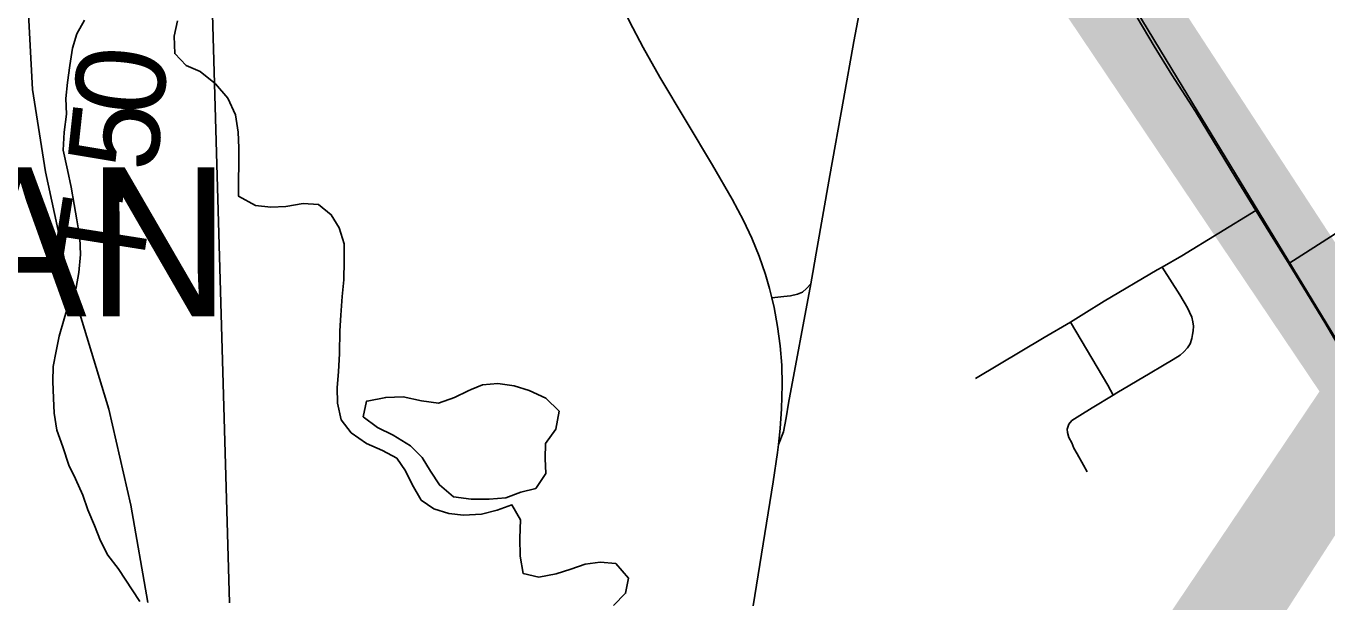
# Model space of a CAD drawing. Extents: x 0 to 34, y 0 to 22.
# Drawn here: x 24.267 to 25.094, y 15.37 to 15.736 of the extents above; entities that cross this region are included whole.
import ezdxf

# ---------------------------------------------------------------- set-up
doc = ezdxf.new("R2010")
doc.units = 0
for name, color, linetype in [('GM_X_City_Street', 7, 'Continuous'), ('GM_X_Corporation', 7, 'Continuous'), ('GM_X_Corporation_Text', 7, 'Continuous'), ('GM_X_Minor_Lake', 7, 'Continuous'), ('GM_X_Minor_River', 7, 'Continuous'), ('GM_X_Rail_Line', 7, 'Continuous'), ('GM_X_State_Location', 7, 'Continuous'), ('GM_X_State_Route', 7, 'Continuous'), ('GM_X_Township_Road_Text', 7, 'Continuous'), ('GM_X_US_Route', 7, 'Continuous'), ('SH_Text', 7, 'Continuous')]:
    doc.layers.add(name, color=color, linetype=linetype)

msp = doc.modelspace()

# ---------------------------------------------------------------- linework, layer by layer
at = {"layer": 'GM_X_City_Street'}
for points in [[(24.74536, 15.47013), (24.7487, 15.4782), (24.7504, 15.48722), (24.75186, 15.49649), (24.76593, 15.57224), (24.76719, 15.57943), (24.76935, 15.59172), (24.77803, 15.64122), (24.78684, 15.68955), (24.7933, 15.72624), (24.79909, 15.75669), (24.81704, 15.85353), (24.83005, 15.92365), (24.83706, 15.96719)], [(24.87069, 15.51205), (24.91425, 15.53818), (24.93116, 15.54787), (24.93955, 15.55322), (24.95246, 15.56119), (24.98618, 15.58112), (24.98927, 15.58282), (25.00193, 15.59016), (25.04895, 15.61884)], [(24.94166, 15.45285), (24.93934, 15.45695), (24.93524, 15.46426), (24.93328, 15.46783), (24.93187, 15.47123), (24.93005, 15.47469), (24.92915, 15.47777), (24.929, 15.48), (24.92998, 15.48305), (24.93186, 15.48538), (24.93693, 15.48867), (24.94493, 15.49342), (24.95814, 15.50152), (24.96055, 15.503), (24.98181, 15.51561), (24.98962, 15.52026), (24.99633, 15.52414), (25.00072, 15.52695), (25.00318, 15.52917), (25.00553, 15.53169), (25.0071, 15.53417), (25.00817, 15.53755), (25.0087, 15.54005), (25.00898, 15.54232), (25.00921, 15.54549), (25.00892, 15.54813), (25.00829, 15.55118), (25.00685, 15.55434), (25.00548, 15.55694), (25.00058, 15.56533), (24.98927, 15.58282)], [(24.74121, 15.56342), (24.74877, 15.56418), (24.75303, 15.5646), (24.7575, 15.56566), (24.76067, 15.56697), (24.7633, 15.56934), (24.76593, 15.57224)], [(24.95814, 15.50152), (24.95478, 15.50787), (24.93116, 15.54787)]]:
    msp.add_lwpolyline(points, dxfattribs=at)
at = {"layer": 'GM_X_Corporation'}
for points in [[(24.39649, 15.36959), (24.38041, 15.92726), (24.38056, 15.92741), (24.39462, 15.94223), (24.40352, 15.95099), (24.41056, 15.95718), (24.41794, 15.96294), (24.42562, 15.9683), (24.45188, 15.98487), (24.48106, 16.0025), (24.53434, 16.03428), (24.53774, 16.03643), (24.54532, 16.04049), (24.573, 16.05699), (24.59313, 16.06938), (24.53129, 16.17458), (24.52067, 16.16701), (24.50344, 16.24261), (24.48872, 16.26543)], [(25.16052, 15.64334), (25.0698, 15.58526), (25.09255, 15.54836), (25.10471, 15.52765)]]:
    msp.add_lwpolyline(points, dxfattribs=at)
at = {"layer": 'GM_X_Minor_Lake'}
for points in [[(24.48399, 15.49775), (24.48361, 15.49775), (24.4814, 15.48785), (24.49056, 15.48106), (24.50047, 15.47619), (24.51154, 15.46941), (24.51881, 15.46185), (24.52419, 15.45314), (24.52995, 15.44444), (24.53874, 15.43689), (24.55014, 15.43544), (24.56154, 15.43551), (24.57217, 15.43634), (24.58164, 15.43982), (24.59112, 15.44216), (24.59752, 15.45171), (24.59707, 15.46121), (24.59738, 15.47072), (24.60378, 15.47988), (24.60598, 15.4913), (24.59756, 15.49961), (24.58689, 15.50449), (24.57737, 15.50747), (24.56711, 15.50893), (24.55723, 15.5081), (24.55009, 15.50507)], [(24.55009, 15.50507), (24.54814, 15.50424), (24.53944, 15.50001), (24.5292, 15.49652), (24.51856, 15.49797), (24.50676, 15.50056), (24.49575, 15.50011), (24.48399, 15.49775)]]:
    msp.add_lwpolyline(points, dxfattribs=at)
at = {"layer": 'GM_X_Minor_River'}
for points in [[(24.30413, 15.73993), (24.29925, 15.73116), (24.29666, 15.72202), (24.29483, 15.71098), (24.29339, 15.70033), (24.29232, 15.69005), (24.29277, 15.68017), (24.29133, 15.66876), (24.29065, 15.65734), (24.2934, 15.64482), (24.29575, 15.6338), (24.29773, 15.62279), (24.29932, 15.61292), (24.30129, 15.60152), (24.30175, 15.59088), (24.30069, 15.57947), (24.29885, 15.56995), (24.29436, 15.56004), (24.29139, 15.55013), (24.28805, 15.53909), (24.28622, 15.52957), (24.28439, 15.51967), (24.28407, 15.51016), (24.28453, 15.49952), (24.28497, 15.49002), (24.28657, 15.47938), (24.29044, 15.46876), (24.29432, 15.457), (24.29856, 15.44828), (24.30319, 15.43805), (24.3063, 15.42856), (24.31054, 15.4187), (24.31441, 15.40884), (24.31903, 15.39975), (24.32555, 15.39142), (24.33931, 15.37037)], [(24.3634, 15.73955), (24.36119, 15.72965), (24.36164, 15.71863), (24.36892, 15.71107), (24.37768, 15.70733), (24.38761, 15.6994), (24.39527, 15.69033), (24.40028, 15.67972), (24.40188, 15.6687), (24.40233, 15.65882), (24.4024, 15.64817), (24.40209, 15.63829), (24.40216, 15.62802), (24.41284, 15.62201), (24.42273, 15.62093), (24.43222, 15.62137), (24.44322, 15.62334), (24.4531, 15.62264), (24.46113, 15.61623), (24.46612, 15.6079), (24.46924, 15.59765), (24.46931, 15.58701), (24.46901, 15.57484), (24.46795, 15.56419), (24.46727, 15.55239), (24.46658, 15.5425), (24.4663, 15.52805), (24.46562, 15.51626), (24.46493, 15.50637), (24.465, 15.49649), (24.46735, 15.48586), (24.47387, 15.47754), (24.48342, 15.47075), (24.4937, 15.46626), (24.50285, 15.46137), (24.50823, 15.45342), (24.51247, 15.4447), (24.51824, 15.43486), (24.52625, 15.4292), (24.53577, 15.42622), (24.54528, 15.42514), (24.55667, 15.42597), (24.56653, 15.42832), (24.576, 15.4318), (24.58138, 15.42233), (24.58109, 15.41054), (24.58117, 15.39914), (24.58314, 15.38812), (24.59303, 15.3859), (24.60404, 15.38788), (24.61351, 15.39098), (24.62261, 15.39408), (24.6321, 15.39528), (24.64198, 15.39458), (24.65002, 15.38513), (24.64819, 15.37561), (24.64054, 15.3679)]]:
    msp.add_lwpolyline(points, dxfattribs=at)
at = {"layer": 'GM_X_Rail_Line'}
for points in [[(24.34445, 15.36972), (24.33361, 15.43161), (24.31966, 15.49253), (24.2932, 15.57967), (24.2795, 15.64344), (24.27116, 15.69579), (24.26789, 15.756), (24.27488, 15.80887), (24.28351, 15.8528), (24.29511, 15.89794), (24.31048, 15.94231), (24.33198, 15.99148), (24.35338, 16.02676), (24.37936, 16.05929), (24.40652, 16.09479), (24.40734, 16.0965), (24.47145, 16.17882), (24.50648, 16.22312), (24.56861, 16.28309), (24.58796, 16.29887)], [(24.58796, 16.29887), (24.58946, 16.28505), (24.59459, 16.27395), (24.60315, 16.26328), (24.61725, 16.25945), (24.63412, 16.2601), (24.64608, 16.26054), (24.65933, 16.25713), (24.67237, 16.24155), (24.99907, 15.70283), (25.19172, 15.38629), (25.20806, 15.3677)]]:
    msp.add_lwpolyline(points, dxfattribs=at)
at = {"layer": 'GM_X_State_Route'}
for points in [[(25.05815, 15.60395), (25.05106, 15.61544), (25.04895, 15.61884), (25.03632, 15.6393), (25.01051, 15.68178), (24.99556, 15.70522), (24.98426, 15.72334), (24.97344, 15.74165), (24.95464, 15.77242), (24.95036, 15.77943), (24.93468, 15.8051), (24.91837, 15.83153), (24.91316, 15.83925), (24.90548, 15.85264), (24.89593, 15.86861), (24.88497, 15.88648), (24.87363, 15.90583), (24.85123, 15.94303), (24.83706, 15.96719)], [(24.74121, 15.56342), (24.73981, 15.56927), (24.7372, 15.57817), (24.73312, 15.58984), (24.72842, 15.60128), (24.72315, 15.61247), (24.71593, 15.62617), (24.70357, 15.64768), (24.67004, 15.70359), (24.65933, 15.72253), (24.65069, 15.73908), (24.64269, 15.75593), (24.63522, 15.77299)], [(25.14958, 15.45132), (25.14478, 15.45883), (25.14224, 15.46311), (25.13763, 15.47085), (25.10492, 15.5271), (25.09277, 15.5478), (25.07002, 15.5847), (25.05815, 15.60395)], [(24.74536, 15.47013), (24.74649, 15.4804), (24.74738, 15.49273), (24.74777, 15.50816), (24.74747, 15.52049), (24.7465, 15.53282), (24.74491, 15.54509), (24.74269, 15.55725), (24.74121, 15.56342)], [(24.72926, 15.36764), (24.74213, 15.44651), (24.74479, 15.46499), (24.74536, 15.47013)]]:
    msp.add_lwpolyline(points, dxfattribs=at)
at = {"layer": 'GM_X_US_Route'}
for points in [[(24.63522, 15.77299), (24.64269, 15.75593), (24.65069, 15.73908), (24.65933, 15.72253), (24.67004, 15.70359), (24.70357, 15.64768), (24.71593, 15.62617), (24.72315, 15.61247), (24.72842, 15.60128), (24.73312, 15.58984), (24.7372, 15.57817), (24.73981, 15.56927), (24.74121, 15.56342)], [(24.74121, 15.56342), (24.74269, 15.55725), (24.74491, 15.54509), (24.7465, 15.53282), (24.74747, 15.52049), (24.74777, 15.50816), (24.74738, 15.49273), (24.74649, 15.4804), (24.74536, 15.47013)], [(24.74536, 15.47013), (24.74479, 15.46499), (24.74213, 15.44651), (24.72926, 15.36764)]]:
    msp.add_lwpolyline(points, dxfattribs=at)

# ---------------------------------------------------------------- texts
at = {"layer": 'GM_X_Corporation_Text'}
msp.add_text('MILAN', height=0.094697, rotation=0.00001, dxfattribs=at).set_placement((24.01013, 15.5516))
at = {"layer": 'GM_X_State_Location'}
msp.add_text('601', height=0.000189, rotation=0.00001, dxfattribs=at).set_placement((25.08655, 15.40999))
at = {"layer": 'GM_X_Township_Road_Text'}
for s, rotation, p in [('0', 84.37439, (24.35345, 15.67797)), ('5', 83.80241, (24.3496, 15.64256)), ('-', 82.87411, (24.34659, 15.61841)), ('T', 81.02347, (24.33968, 15.57445))]:
    msp.add_text(s, height=0.05682, rotation=rotation, dxfattribs=at).set_placement(p)
at = {"layer": 'SH_Text'}
msp.add_text('X', height=0.56, dxfattribs=at).set_placement((24.87659, 15.21296))

doc.saveas('drawing.dxf')
